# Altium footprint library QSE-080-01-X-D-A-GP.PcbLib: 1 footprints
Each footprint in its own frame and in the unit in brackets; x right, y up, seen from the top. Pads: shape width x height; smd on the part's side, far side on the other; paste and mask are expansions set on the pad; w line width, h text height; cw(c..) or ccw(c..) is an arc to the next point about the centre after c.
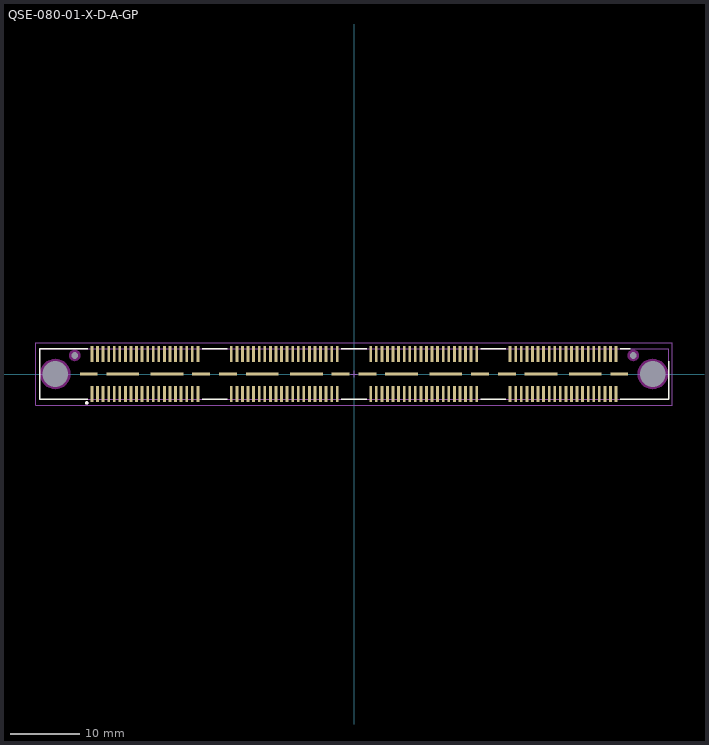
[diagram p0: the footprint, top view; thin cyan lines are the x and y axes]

## QSE-080-01-X-D-A-GP [mm] "0.80mm pitch, 160 pin, high speed socket strip; w/guide posts"
height 3.25
pads (180):
  rect 0.4x2.25 smd mask+0: 1(-37.6,-2.865) 2(-37.6,2.865) 3(-36.8,-2.865) 4(-36.8,2.865) 5(-36,-2.865) 6(-36,2.865) 7(-35.2,-2.865) 8(-35.2,2.865) 9(-34.4,-2.865) 10(-34.4,2.865) 11(-33.6,-2.865) 12(-33.6,2.865) 13(-32.8,-2.865) 14(-32.8,2.865) 15(-32,-2.865) 16(-32,2.865) 17(-31.2,-2.865) 18(-31.2,2.865) 19(-30.4,-2.865) 20(-30.4,2.865) 21(-29.6,-2.865) 22(-29.6,2.865) 23(-28.8,-2.865) 24(-28.8,2.865) 25(-28,-2.865) 26(-28,2.865) 27(-27.2,-2.865) 28(-27.2,2.865) 29(-26.4,-2.865) 30(-26.4,2.865) 31(-25.6,-2.865) 32(-25.6,2.865) 33(-24.8,-2.865) 34(-24.8,2.865) 35(-24,-2.865) 36(-24,2.865) 37(-23.2,-2.865) 38(-23.2,2.865) 39(-22.4,-2.865) 40(-22.4,2.865) 41(-17.6,-2.865) 42(-17.6,2.865) 43(-16.8,-2.865) 44(-16.8,2.865) 45(-16,-2.865) 46(-16,2.865) 47(-15.2,-2.865) 48(-15.2,2.865) 49(-14.4,-2.865) 50(-14.4,2.865) 51(-13.6,-2.865) 52(-13.6,2.865) 53(-12.8,-2.865) 54(-12.8,2.865) 55(-12,-2.865) 56(-12,2.865) 57(-11.2,-2.865) 58(-11.2,2.865) 59(-10.4,-2.865) 60(-10.4,2.865) 61(-9.6,-2.865) 62(-9.6,2.865) 63(-8.8,-2.865) 64(-8.8,2.865) 65(-8,-2.865) 66(-8,2.865) 67(-7.2,-2.865) 68(-7.2,2.865) 69(-6.4,-2.865) 70(-6.4,2.865) 71(-5.6,-2.865) 72(-5.6,2.865) 73(-4.8,-2.865) 74(-4.8,2.865) 75(-4,-2.865) 76(-4,2.865) 77(-3.2,-2.865) 78(-3.2,2.865) 79(-2.4,-2.865) 80(-2.4,2.865) 81(2.4,-2.865) 82(2.4,2.865) 83(3.2,-2.865) 84(3.2,2.865) 85(4,-2.865) 86(4,2.865) 87(4.8,-2.865) 88(4.8,2.865) 89(5.6,-2.865) 90(5.6,2.865) 91(6.4,-2.865) 92(6.4,2.865) 93(7.2,-2.865) 94(7.2,2.865) 95(8,-2.865) 96(8,2.865) 97(8.8,-2.865) 98(8.8,2.865) 99(9.6,-2.865) 100(9.6,2.865) 101(10.4,-2.865) 102(10.4,2.865) 103(11.2,-2.865) 104(11.2,2.865) 105(12,-2.865) 106(12,2.865) 107(12.8,-2.865) 108(12.8,2.865) 109(13.6,-2.865) 110(13.6,2.865) 111(14.4,-2.865) 112(14.4,2.865) 113(15.2,-2.865) 114(15.2,2.865) 115(16,-2.865) 116(16,2.865) 117(16.8,-2.865) 118(16.8,2.865) 119(17.6,-2.865) 120(17.6,2.865) 121(22.4,-2.865) 122(22.4,2.865) 123(23.2,-2.865) 124(23.2,2.865) 125(24,-2.865) 126(24,2.865) 127(24.8,-2.865) 128(24.8,2.865) 129(25.6,-2.865) 130(25.6,2.865) 131(26.4,-2.865) 132(26.4,2.865) 133(27.2,-2.865) 134(27.2,2.865) 135(28,-2.865) 136(28,2.865) 137(28.8,-2.865) 138(28.8,2.865) 139(29.6,-2.865) 140(29.6,2.865) 141(30.4,-2.865) 142(30.4,2.865) 143(31.2,-2.865) 144(31.2,2.865) 145(32,-2.865) 146(32,2.865) 147(32.8,-2.865) 148(32.8,2.865) 149(33.6,-2.865) 150(33.6,2.865) 151(34.4,-2.865) 152(34.4,2.865) 153(35.2,-2.865) 154(35.2,2.865) 155(36,-2.865) 156(36,2.865) 157(36.8,-2.865) 158(36.8,2.865) 159(37.6,-2.865) 160(37.6,2.865)
  rect 2.55x0.45 smd mask+0: 161(-38.065,0) 164(-21.935,0) 165(-18.065,0) 168(-1.935,0) 169(1.935,0) 172(18.065,0) 173(21.935,0) 176(38.065,0)
  rect 4.7x0.45 smd mask+0: 162(-33.175,0) 163(-26.825,0) 166(-13.175,0) 167(-6.825,0) 170(6.825,0) 171(13.175,0) 174(26.825,0) 175(33.175,0)
  round 0.5 hole 1 unplated mask+0: 177(-40.065,2.665) 178(40.065,2.665)
  round 1 hole 3.7 unplated mask+0: 179(-42.86,0) 180(42.86,0)
Top Overlay:
  circle w0.25: c-38.35,-4.15 r0.125
  lines w0.2: -38.2,-3.6 -45.1,-3.6 -45.1,3.6 -38.2,3.6 ; -21.8,-3.6 -18.2,-3.6 ; -21.8,3.6 -18.2,3.6 ; -1.8,-3.6 1.8,-3.6 ; -1.8,3.6 1.8,3.6 ; 18.2,-3.6 21.8,-3.6 ; 18.2,3.6 21.8,3.6 ; 38.2,-3.6 45.15,-3.6 45.15,1.85 ; 38.2,3.6 39.65,3.6
Keep-Out Layer:
  pour cut-out: 45.02,0 44.979,0.421 44.856,0.827 44.656,1.2 44.388,1.528 44.06,1.796 43.687,1.996 43.281,2.119 42.86,2.16 42.439,2.119 42.033,1.996 41.66,1.796 41.332,1.528 41.064,1.2 40.864,0.827 40.741,0.421 40.7,0 40.741,-0.421 40.864,-0.827 41.064,-1.2 41.332,-1.528 41.66,-1.796 42.033,-1.996 42.439,-2.119 42.86,-2.16 43.281,-2.119 43.687,-1.996 44.06,-1.796 44.388,-1.528 44.656,-1.2 44.856,-0.827 44.979,-0.421
  pour cut-out: 40.872,2.665 40.844,2.874 40.764,3.068 40.636,3.236 40.468,3.364 40.274,3.444 40.065,3.472 39.856,3.444 39.662,3.364 39.494,3.236 39.366,3.068 39.286,2.874 39.258,2.665 39.286,2.456 39.366,2.262 39.494,2.094 39.662,1.966 39.856,1.886 40.065,1.858 40.274,1.886 40.468,1.966 40.636,2.094 40.764,2.262 40.844,2.456
  pour cut-out: -40.7,0 -40.741,0.421 -40.864,0.827 -41.064,1.2 -41.332,1.528 -41.66,1.796 -42.033,1.996 -42.439,2.119 -42.86,2.16 -43.281,2.119 -43.687,1.996 -44.06,1.796 -44.388,1.528 -44.656,1.2 -44.856,0.827 -44.979,0.421 -45.02,0 -44.979,-0.421 -44.856,-0.827 -44.656,-1.2 -44.388,-1.528 -44.06,-1.796 -43.687,-1.996 -43.281,-2.119 -42.86,-2.16 -42.439,-2.119 -42.033,-1.996 -41.66,-1.796 -41.332,-1.528 -41.064,-1.2 -40.864,-0.827 -40.741,-0.421
  pour cut-out: -39.258,2.665 -39.286,2.874 -39.366,3.068 -39.494,3.236 -39.662,3.364 -39.856,3.444 -40.065,3.472 -40.274,3.444 -40.468,3.364 -40.636,3.236 -40.764,3.068 -40.844,2.874 -40.872,2.665 -40.844,2.456 -40.764,2.262 -40.636,2.094 -40.468,1.966 -40.274,1.886 -40.065,1.858 -39.856,1.886 -39.662,1.966 -39.494,2.094 -39.366,2.262 -39.286,2.456
Mechanical 12:
  lines w0.001: -45.1,-3.6 -45.1,3.6 45.15,3.6 45.15,-3.6 -45.1,-3.6
Mechanical 13:
  circle w0.25: c-38.35,-4.15 r0.125
  lines w0.1: -45.1,-3.6 -45.1,3.6 45.15,3.6 45.15,-3.6 -45.1,-3.6
  text ".Designator" at 0.381,0.254 h1.52
Mechanical 15:
  lines w0.05: -0.5,0 0.5,0 ; 0,-0.5 0,0.5 ; -45.65,-4.5 -45.65,4.5 45.65,4.5 45.65,-4.5 -45.65,-4.5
